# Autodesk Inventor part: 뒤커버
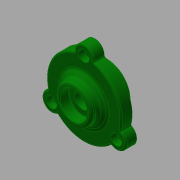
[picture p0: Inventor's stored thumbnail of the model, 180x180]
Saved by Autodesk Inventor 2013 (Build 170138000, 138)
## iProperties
Created: 2016-05
Part Number: 뒤커버
Document SubType Name: Modeling
Designer: mduedu
Density: 2.71 g/cm^3
Material: 알루미늄 6061
Author: mduedu
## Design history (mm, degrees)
sketch "스케치1"
  geometry: C1 r 17.5 at (0, 0); C2 r 27.5 at (0, 0); 1 further point
  constraints: 2 centre point, 2 coincident
  dimensions: "d33" = 55 diameter of C2; "d34" = 35 diameter of C1
extrude "돌출1" new body sketch "스케치1" distance "d0" = 8; taper "d1" = 0 deg
extrude "돌출2" join sketch "스케치1" distance "d2" = 8; taper "d3" = 0 deg; dims "d35" = 9, "d36" = 0
sketch "스케치5"
  geometry: L1 (-27.5, 8)-(27.5, 8) reference; L2 (0, 0)-(0, 15); L3 (-27.5, 0)-(27.5, 0) reference; L4 (17.5, 8)-(0, 8); A1 r 25.375 centre (0, -10.375) between (17.5, 8) and (0, 15)
  constraints: 4 end point, 3 point on line, 2 point on circle, 1 centre point, 1 midpoint, 1 perpendicular
  dimensions: "d37" = 17.5 distance from line of L2 L4.start; "d39" = 7 distance from line of L1 L2.end
revolve "회전2" sketch "스케치5" stored, may be unused: angle "d40" = 90 deg
node "작업 평면1"
sketch "스케치6"
  geometry: C1 r 13.5 at (0, 0); 1 further point
  constraints: 1 centre point, 1 coincident
  dimensions: "d42" = 27 diameter of C1
extrude "돌출4" join sketch "스케치6" stored distance "d43" = 10; taper "d44" = 0 deg
sketch "스케치4"
  geometry: L1 (0, -9)-(0, 16); L2 (-15, -9)-(-15, 0); L3 (-15, 0)-(-10, 0); L4 (-10, 0)-(-10, 3); L5 (-10, 3)-(-6, 3); L6 (-6, 3)-(-6, 9); L7 (-6, 9)-(-10, 9); L8 (-10, 9)-(-10, 16); L9 (17.5, -9)-(-17.5, -9) reference; L10 (-13.5, 16)-(13.5, 16) reference; 1 further point
  constraints: 16 end point, 6 parallel, 3 point on line, 2 midpoint, 1 perpendicular, 1 vertical
  dimensions: "d15" = 30 diameter of L2 L1; "d16" = 20 diameter of L8 L1; "d18" = 9 distance of L2.start L2.end; "d19" = 3 distance of L3.end L4.end; "d20" = 20 diameter of L4 L1; "d21" = 12 diameter of L6 L1; "d45" = 7 distance of L7.end L8.end
revolve "회전1" sketch "스케치4" stored, may be unused: angle "d22" = 90 deg
fillet "모깎기2" dims "d23" = 3
fillet "모깎기3" dims "d24" = 0.3
chamfer "모따기2" distance "d46" = 0.5; stored, may be unused: second distance "d47" = 2, angle "d48" = 45 deg
fillet "모깎기4" dims "d49" = 3
fillet "모깎기5" dims "d50" = 2
sketch "스케치7"
  geometry: C1 r 7 at (0, 27.5); 2 further points
  constraints: 3 vertical alignment, 1 centre point, 2 other
  dimensions: "d54" = 14 diameter of C1
extrude "돌출5" join sketch "스케치7" stored distance "d55" = 10; taper "d56" = 0 deg
fillet "모깎기6" dims "d57" = 1
fillet "모깎기7" dims "d61" = 1
sketch "스케치8" dims "d62" = 55 (derived)
  geometry: C1 r 18.661 at (0, 0) reference; A1 r 2 centre (-7.999, 27.355) between (-7.437, 25.435) and (-5.999, 27.391) reference; A2 r 26.5 centre (0, 0) between (-7.437, 25.435) and (-25.746, -6.277) reference; A3 r 2 centre (-27.689, -6.75) between (-26.721, -8.5) and (-25.746, -6.277) reference; A4 r 6 centre (-23.816, -13.75) between (-26.721, -8.5) and (-20.722, -18.891) reference; A5 r 2 centre (-19.69, -20.604) between (-18.309, -19.158) and (-20.722, -18.891) reference; A6 r 26.5 centre (0, 0) between (-18.309, -19.158) and (18.309, -19.158) reference; A7 r 2 centre (19.69, -20.604) between (20.722, -18.891) and (18.309, -19.158) reference; A8 r 6 centre (23.816, -13.75) between (20.722, -18.891) and (26.721, -8.5) reference; A9 r 2 centre (27.689, -6.75) between (25.746, -6.277) and (26.721, -8.5) reference; A10 r 26.5 centre (0, 0) between (25.746, -6.277) and (7.437, 25.435) reference; A11 r 2 centre (7.999, 27.355) between (5.999, 27.391) and (7.437, 25.435) reference; A12 r 6 centre (0, 27.5) between (5.999, 27.391) and (-5.999, 27.391) reference; 4 further points
  constraints: 2 coincident, 1 vertical alignment, 6 other
  dimensions: "d65" = 360 deg dimension on A2.centre point (0, 27.5) (derived)
sketch "스케치9"
  geometry: 3 further points
  constraints: 3 other
hole "구멍2" sketch "스케치9" at (-23.816, -13.75), (23.816, -13.75), (0, 27.5) diameter "d67" = 4.5; stored, may be unused: countersink angle "d71" = 90 deg, drill point angle "d73" = 0 deg; dims "d68" = 6, "d69" = 8, "d70" = 4.6, "d72" = 8
node "솔리드1"
pattern_circular "원형 패턴1" dims angle "d59" = 360 deg
other parameters: "d41" = 8
